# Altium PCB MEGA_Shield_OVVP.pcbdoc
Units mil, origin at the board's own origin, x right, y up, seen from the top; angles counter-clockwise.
Board outline 3935.43 x 2978.74 mil, 2 copper layers (Top Layer, Bottom Layer); 127 components, 86 nets, 395 pads, 316 vias.
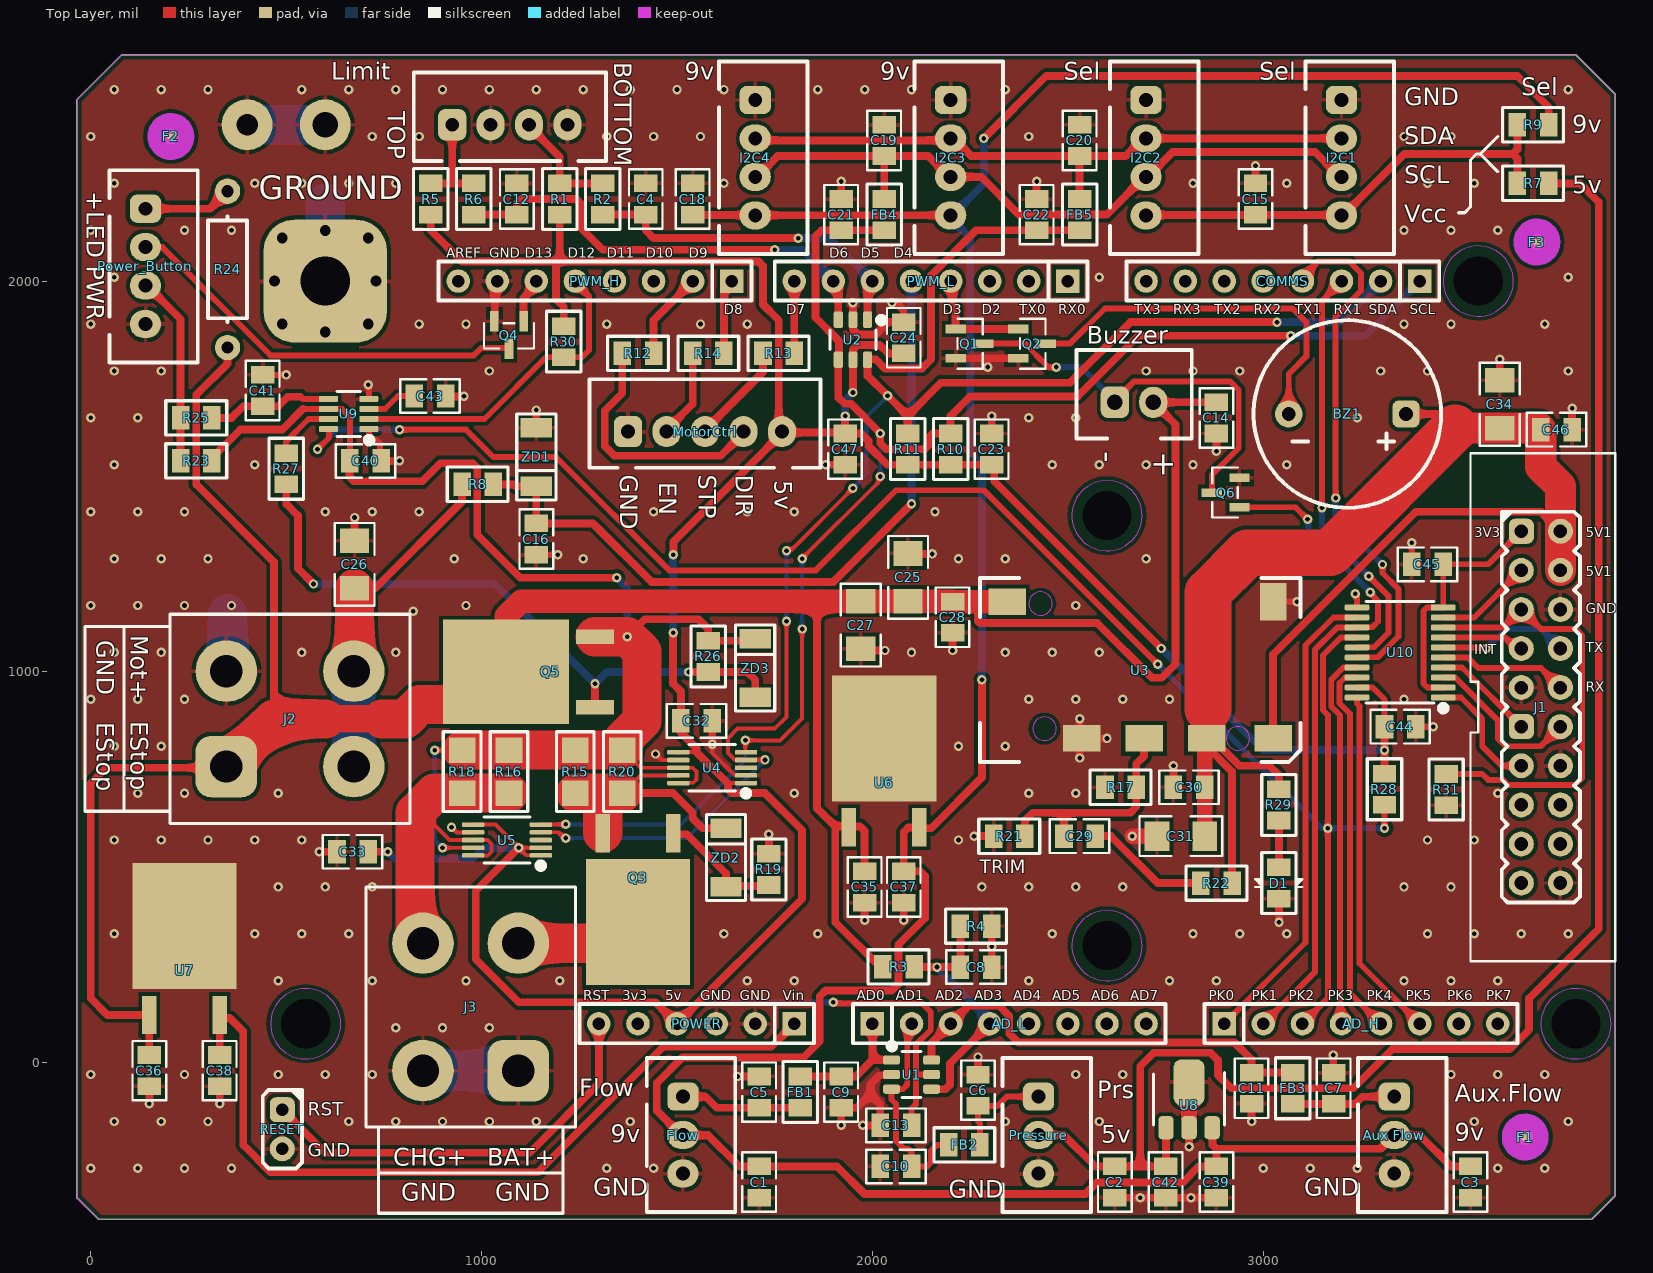
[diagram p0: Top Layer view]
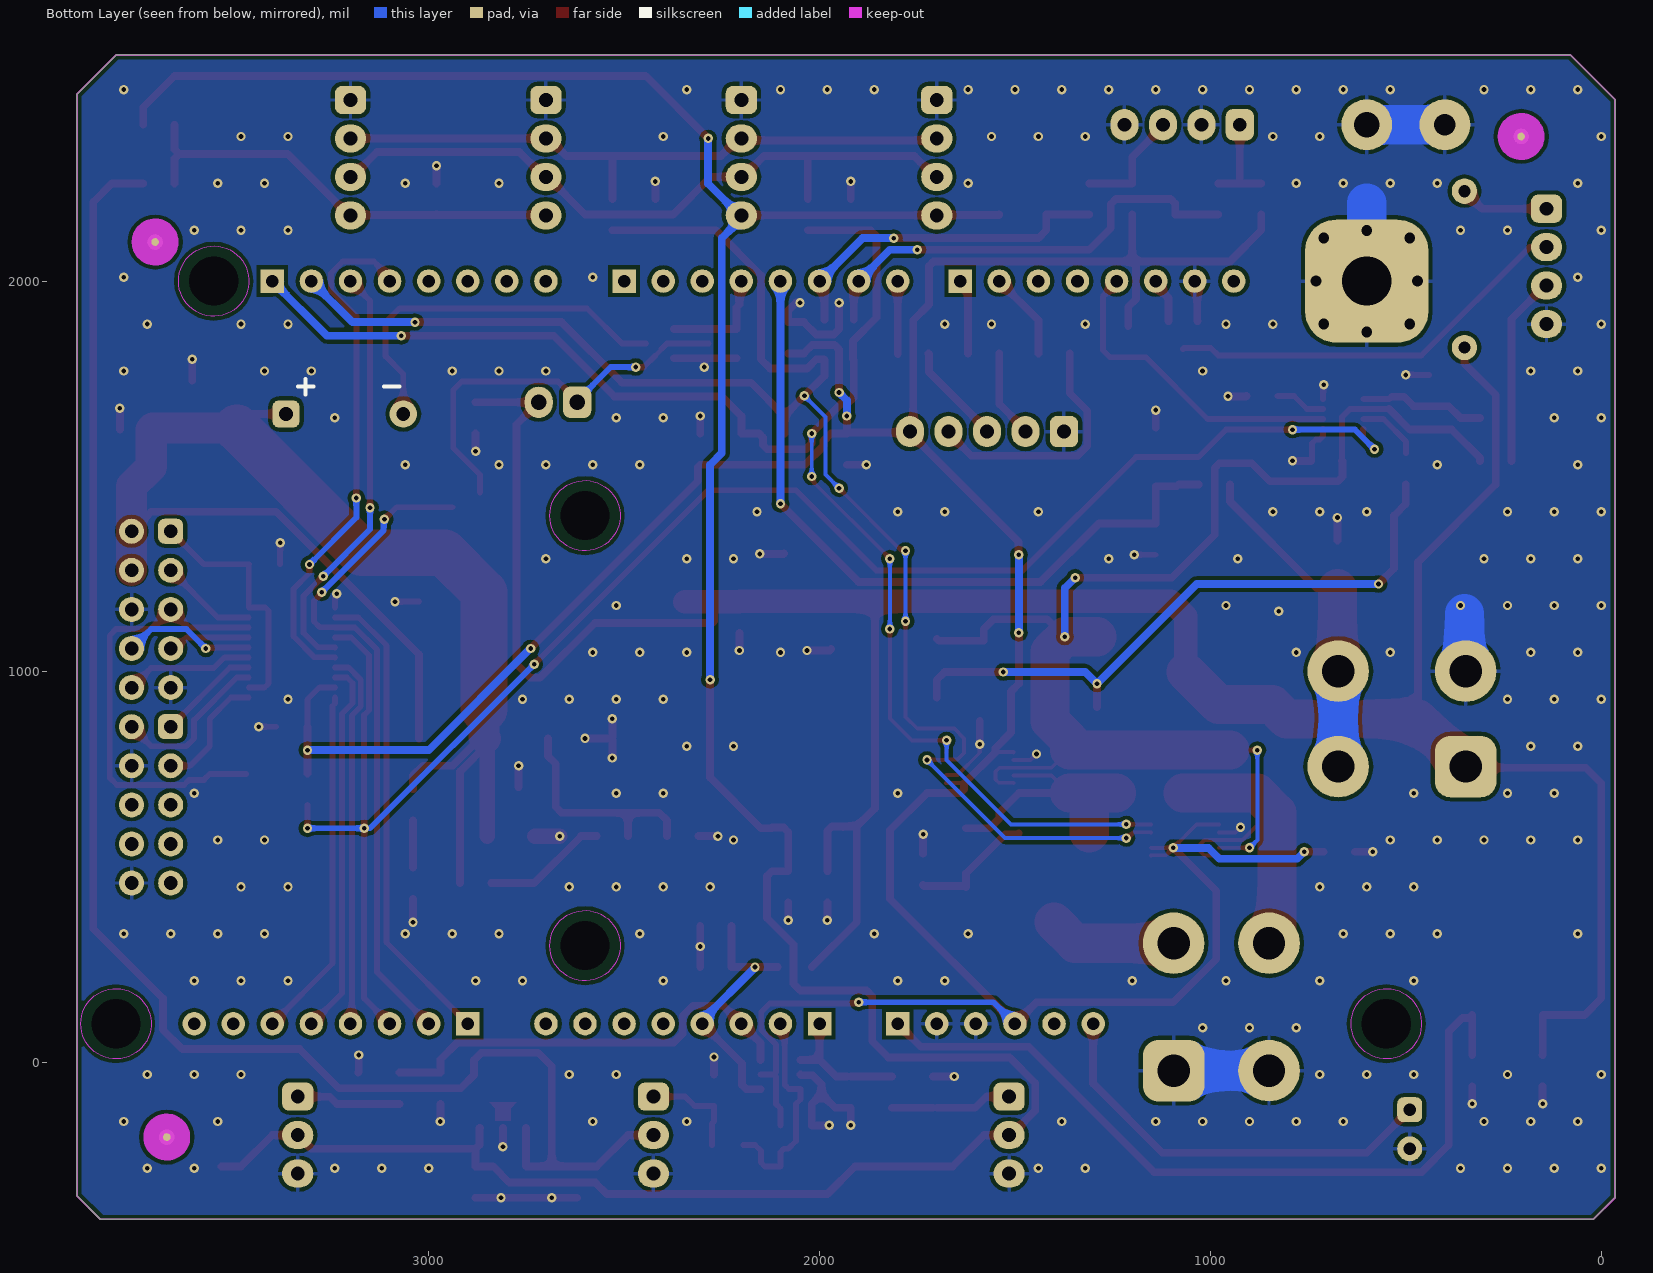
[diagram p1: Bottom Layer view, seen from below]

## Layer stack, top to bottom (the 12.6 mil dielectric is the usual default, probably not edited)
Top Solder: solder mask 0.4, Solder Resist, Dk 3.5
Top Layer: signal copper 1.4
Dielectric1: dielectric 12.6, FR-4, Dk 4.8
Bottom Layer: signal copper 1.4
Bottom Solder: solder mask 0.4, Solder Resist, Dk 3.5

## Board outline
-35.43,-344.57 20,-400 3840,-400 3900,-340 3900,50 3900,1600 3900,2477.95 3799.21,2578.74 78.74,2578.74 -35.43,2464.57

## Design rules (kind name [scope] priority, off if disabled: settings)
Clearance Bot-Poly-Clearance [InNamedPolygon('Bot-GND')] p1: gap=10 ignorepadtopadclearanceinfootprint=FALSE
Clearance Top-Poly-Clearance [InNamedPolygon('Top-GND')] p2: gap=10 ignorepadtopadclearanceinfootprint=FALSE except(0: Arc-Hole Track-Hole SMDPad-Hole THPad-Hole Via-Hole Fill-Hole Poly-Hole Region-Hole Text-Hole)
Clearance [All] p3: gap=6 ignorepadtopadclearanceinfootprint=FALSE
PolygonConnect PolygonConnect_DPAK [All vs HasFootprint('TO-252-3') OR HasFootprint('DC-DC ProLynx')] p1: connectstyle=Direct reliefconductorwidth=10 reliefentries=4 polygonreliefangle="90 Angle" airgapwidth=10
PolygonConnect PolygonConnect_Via [All vs isVia] p2: connectstyle=Direct reliefconductorwidth=10 reliefentries=4 polygonreliefangle="90 Angle" airgapwidth=10
PolygonConnect PolygonConnect_1 [All] p3: connectstyle=Relief reliefconductorwidth=10 reliefentries=4 polygonreliefangle="90 Angle" airgapwidth=10
RoutingVias [All] p1: holewidth=12 width=24 viastyle="Through Hole" minholewidth=12 minwidth=24 maxholewidth=31 maxwidth=50
SilkToSolderMaskClearance SilkscreenOverComponentPads [IsPad] p1: minsilkscreentomaskgap=10 clearancetoexposedcopper=TRUE
SolderMaskExpansion SolderMaskExpansion_Via [IsVia] p1: expansion=-39.37 soldermaskfromhole=TRUE
SolderMaskExpansion [All] p2: expansion=4
Width [All] p1: maxlimit=200 minlimit=10 preferedwidth=20
29 further rules are at their usual default settings.

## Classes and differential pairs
component class 03_RPi: C44 C45 C46 J1 R31 U10
component class 02_Power: C25 C26 C27 C28 C29 C30 C31 C32 C33 C34 C35 C36 C37 C38 C39 C40 C41 C42 C43 D1 J2 J3 Power_Button Q3 Q4 Q5 R15 R16 R17 R18 R19 R20 R21 R22 R23 R24 R25 R26 R27 R28 R29 R30 U3 U4 U5 U6 U7 U8 U9 ZD2 ZD3
component class 01_Shield: AD_H AD_L Analog "Aux Flow" Buzzer BZ1 C1 C2 C3 C4 C5 C6 C7 C8 C9 C10 C11 C12 C13 C14 C15 C16 C18 C19 C20 C21 C22 C23 C24 C47 COMMS F1 F2 F3 FB1 FB2 FB3 FB4 FB5 Flow I2C1 I2C2 I2C3 I2C4 Limit MotorCtrl POWER Pressure PWM_H PWM_L Q1 Q2 Q6 R1 R2 R3 R4 R5 R6 R7 R8 R9 R10 R11 R12 R13 R14 RESET U1 U2 ZD1

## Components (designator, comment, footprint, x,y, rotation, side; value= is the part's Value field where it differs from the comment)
AD_H "AD_H" "Header 8x1 8.5mm" 2900,100 r0 top locked
AD_L "AD_L" "Header 8x1 8.5mm" 2000,100 r0 top locked
"Aux Flow" "3pin JST" "3pin JST XH 2.5mm" 3335,-86.57 r180 top
Buzzer "2pin JST" "2pin JST XH 2.5mm" 2620,1690 r270 top
BZ1 "BUZZER, 12mm X 9.5mm" Buzzer 3365,1660 r90 top
C1 "0.1uF 50V" "C np SMD 0805" 1710,-305 r90 top
C2 "0.1uF 50V" "C np SMD 0805" 2620,-305 r90 top
C3 "0.1uF 50V" "C np SMD 0805" 3530,-305 r90 top
C4 "0.1uF 50V" "C np SMD 0805" 1420,2210 r270 top
C5 "33pF 50V" "C np SMD 0805" 1710,-75 r270 top
C6 "33pF 50V" "C np SMD 0805" 2270,-70 r270 top
C7 "33pF 50V" "C np SMD 0805" 3180,-65 r270 top
C8 "0.1uF 50V" "C np SMD 0805" 2265,245 r180 top
C9 "100pF 50V" "C np SMD 0805" 1920,-75 r90 top
C10 "100pF 50V" "C np SMD 0805" 2060,-265 r0 top
C11 "100pF 50V" "C np SMD 0805" 2970,-65 r90 top
C12 "0.1uF 50V" "C np SMD 0805" 1090,2210 r270 top
C13 "0.1uF 50V" "C np SMD 0805" 2060,-160 r0 top
C14 "0.1uF 50V" "C np SMD 0805" 2880,1650 r90 top
C15 "0.1uF 50V" "C np SMD 0805" 2980,2210 r270 top
C16 "0.1uF 50V" "C np SMD 0805" 1140,1340 r90 top
C18 "0.1uF 50V" "C np SMD 0805" 1540,2210 r270 top
C19 "33pF 50V" "C np SMD 0805" 2030,2360 r90 top
C20 "33pF 50V" "C np SMD 0805" 2530,2360 r270 top
C21 "33pF 50V" "C np SMD 0805" 1920,2170 r90 top
C22 "33pF 50V" "C np SMD 0805" 2420,2170 r270 top
C23 "0.1uF 50V" "C np SMD 0805" 2305,1570 r90 top
C24 "0.1uF 50V" "C np SMD 0805" 2080,1855 r270 top
C25 "10uF 50V" "C np SMD 1206" 2091,1242 r270 top
C26 "10uF 50V" "C np SMD 1206" 675,1275 r90 top
C27 "10uF 50V" "C np SMD 1206" 1970,1120 r90 top
C28 "0.1uF 50V" "C np SMD 0805" 2205,1140 r90 top
C29 "1nF 100V" "C np SMD 0805" 2530,580 r0 top
C30 "0.1uF 50V" "C np SMD 0805" 2810,705 r0 top
C31 "10uF 50V" "C np SMD 1206" 2789,580 r0 top
C32 "0.1uF 50V" "C np SMD 0805" 1550,875 r0 top
C33 "0.1uF 50V" "C np SMD 0805" 670,540 r180 top
C34 "10uF 50V" "C np SMD 1206" 3605,1685 r270 top
C35 "0.1uF 50V" "C np SMD 0805" 1980,450 r90 top
C36 "0.1uF 50V" "C np SMD 0805" 150,-20 r90 top
C37 "2.2uF 50V" "C np SMD 0805" 2080,450 r90 top
C38 "2.2uF 50V" "C np SMD 0805" 330,-20 r90 top
C39 "0.1uF 50V" "C np SMD 0805" 2880,-305 r90 top
C40 "0.1uF 50V" "C np SMD 0805" 703,1540 r180 top
C41 "0.1uF 50V" "C np SMD 0805" 440,1720 r270 top
C42 "2.2uF 50V" "C np SMD 0805" 2750,-305 r90 top
C43 "2.2uF 50V" "C np SMD 0805" 868,1706 r180 top
C44 "0.1uF 50V" "C np SMD 0805" 3350,860 r180 top
C45 "0.1uF 50V" "C np SMD 0805" 3420,1275.43 r0 top
C46 "0.1uF 50V" "C np SMD 0805" 3750,1620 r180 top
C47 "0.1uF 50V" "C np SMD 0805" 1930,1570 r270 top
COMMS "Communication" "Header 8x1 8.5mm" 3400,2000 r180 top
D1 "LED SMD 0805" "LED SMD 0805" 3040,460 r270 top
F1 "FIDUCIAL" FIDUCIAL 3670,-190 r0 top
F2 "FIDUCIAL" FIDUCIAL 205,2370 r270 top
F3 "FIDUCIAL" FIDUCIAL 3700,2100 r0 top
FB1 "400mA" "R SMD 0805" 1815,-75 r270 top
FB2 "400mA" "R SMD 0805" 2235,-210 r0 top
FB3 "400mA" "R SMD 0805" 3075,-65 r270 top
FB4 "400mA" "R SMD 0805" 2030,2170 r270 top
FB5 "400mA" "R SMD 0805" 2530,2170 r270 top
Flow "3pin JST" "3pin JST XH 2.5mm" 1515,-86.57 r180 top
I2C1 "4pin JST" "4pin JST XH 2.5mm" 3200,2463.43 r180 top
I2C2 "4pin JST" "4pin JST XH 2.5mm" 2700,2463.43 r180 top
I2C3 "4pin JST" "4pin JST XH 2.5mm" 2200,2463.43 r180 top
I2C4 "4pin JST" "4pin JST XH 2.5mm" 1700,2463.43 r180 top
J1 "2ROW HEADER 20PIN" "2ROW HEADER 20PIN" 3660,1360 r270 top
J2 "4pin JST VL" "4pin JST VL" 510,880 r270 top
J3 "4pin JST VL" "4pin JST VL" 972.05,142.99 r0 top
Limit "4pin JST" "4pin JST XH 2.5mm" 924.72,2400 r270 top
MotorCtrl "5pin JST" "5pin JST XH 2.5mm" 1374.72,1615 r270 top
POWER "POWER" "Header 6x1 8.5mm" 1800,100 r180 top locked
Power_Button "4pin JST" "4pin JST XH 2.5mm" 140,2185.28 r180 top
Pressure "3pin JST" "3pin JST XH 2.5mm" 2425,-86.57 r180 top
PWM_H "PWM_H" "Header 8x1 8.5mm" 1640,2000 r180 top locked
PWM_L "PWM_L" "Header 8x1 8.5mm" 2500,2000 r180 top locked
Q1 "SOT23" SOT23 2250,1840 r270 top
Q2 "SOT23" SOT23 2410,1840 r270 top
Q3 "DPAK" DPAK 1400,360 r180 top
Q4 "SOT23" SOT23 1070,1860 r180 top
Q5 "DPAK" DPAK 1062.5,1000.16 r90 top
Q6 "SOT23" SOT23 2901.78,1459.01 r90 top
R1 "4.7k" "R SMD 0805" 1200,2210 r270 top
R2 "100" "R SMD 0805" 1310,2210 r270 top
R3 "30k" "R SMD 0805" 2066.69,245.31 r0 top
R4 "10k" "R SMD 0805" 2265,350 r0 top
R5 "4.7k" "R SMD 0805" 870,2210 r270 top
R6 "100" "R SMD 0805" 980,2210 r270 top
R7 "0R" "R SMD 0805" 3690,2250 r180 top
R8 "10k" "R SMD 0805" 990,1480 r180 top
R9 "0R" "R SMD 0805" 3690,2400 r0 top
R10 "3.3k" "R SMD 0805" 2200,1570 r270 top
R11 "3.3k" "R SMD 0805" 2090,1570 r270 top
R12 "33" "R SMD 0805" 1400,1815 r0 top
R13 "33" "R SMD 0805" 1760,1815 r0 top
R14 "33" "R SMD 0805" 1580,1815 r0 top
R15 "10mOhm" "R SMD 1206" 1240,745 r90 top
R16 "10mOhm" "R SMD 1206" 1070,745 r270 top
R17 "15.8k" "R SMD 0805" 2635,705 r0 top
R18 "10mOhm" "R SMD 1206" 950,745 r270 top
R19 "1M" "R SMD 0805" 1735,495 r270 top
R20 "10mOhm" "R SMD 1206" 1360,745 r90 top
R21 "1M" "R SMD 0805" 2350,580 r0 top
R22 "270" "R SMD 0805" 2880,460 r0 top
R23 "10k" "R SMD 0805" 270,1540 r0 top
R24 "1k2" "R L10 D2.5 W6.3" 350,2030 r270 top
R25 "4.7k" "R SMD 0805" 270,1650 r0 top
R26 "200k" "R SMD 0805" 1580,1040 r90 top
R27 "100k" "R SMD 0805" 500,1520 r270 top
R28 "2k" "R SMD 0805" 3310,700 r90 top
R29 "510" "R SMD 0805" 3040,660 r270 top
R30 "10k" "R SMD 0805" 1210,1845 r90 top
R31 "2k" "R SMD 0805" 3467.54,699.03 r90 top
RESET "1ROW HEADER 2PIN" "1ROW HEADER 2PIN" 490,-120 r180 top
U1 "TPD4E001Q" SOT-23-6 2100,-30 r0 top
U2 "TPD4E001Q" SOT-23-6 1950,1850 r270 top
U3 "APXW003A0X3-SRZ" "DC-DC ProLynx" 3085,1230 r180 top
U4 "INA226" VSSOP10-TI 1590,755 r180 top
U5 "INA226" VSSOP10-TI 1065,570 r180 top
U6 "MC78M09" TO-252-3 2030,830 r0 top
U7 "MC78M09" TO-252-3 240,350 r0 top
U8 "AP7370-50Y-13" SOT-89 2810,-108.03 r90 top
U9 "LTC2955TS8-2" TSOT-23-8-LTC 660,1660 r180 top
U10 "TXs/b0108" TSSOP20-TI 3350,1050 r180 top
ZD1 "4.7V" LL34 1140,1550 r270 top
ZD2 "10V" LL34 1625,525 r90 top
ZD3 "10V" LL34 1700,1010 r90 top

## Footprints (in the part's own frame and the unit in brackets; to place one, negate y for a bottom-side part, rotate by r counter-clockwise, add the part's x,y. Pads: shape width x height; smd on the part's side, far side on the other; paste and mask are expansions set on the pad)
"1ROW HEADER 2PIN" [mil] "PEC02SAAN"
  rrect50% 64x64 hole 32: 1(0,0)
  round 64 hole 32: 2(0,100)
  silkscreen extent -50,-50 50,150
"2pin JST XH 2.5mm" [mil] "B2B-XH"
  rrect50% 80x72 hole 39.37: 1(0,0)
  oval 80x72 hole 39.37: 2(0,98.43)
  silkscreen extent -134,-98 93,197
"2ROW HEADER 20PIN" [mil]
  rrect50% 64x64 hole 35: 1(0,0) 11(500,0)
  round 64 hole 35: 2(0,100) 3(100,0) 4(100,100) 5(200,0) 6(200,100) 7(300,0) 8(300,100) 9(400,0) 10(400,100) 12(500,100) 13(600,0) 14(600,100) 15(700,0) 16(700,100) 17(800,0) 18(800,100) 19(900,0) 20(900,100)
  silkscreen extent -200,-130 1100,240
"3pin JST XH 2.5mm" [mil] "B3B-XH"
  rrect50% 80x72 hole 35.43: 1(0,0)
  oval 80x72 hole 35.43: 2(0,98.43) 3(0,196.85)
  silkscreen extent -134,-98 93,295
"4pin JST VL" [mm] "B04P-VL"
  rrect50% 4x4 hole 2.1: 1(3.1,-4.14)
  round 4 hole 2.1: 2(-3.1,-4.14) 3(3.1,4.14) 4(-3.1,4.14)
  silkscreen extent -6.8,-10.8 6.8,7.8
"4pin JST XH 2.5mm" [mil] "B4B-XH"
  rrect50% 80x72 hole 35.43: 1(0,0)
  oval 80x72 hole 35.43: 2(0,98.43) 3(0,196.85) 4(0,295.28)
  silkscreen extent -134,-98 93,394
"5pin JST XH 2.5mm" [mil] "B4B-XH"
  rrect50% 80x72 hole 35.43: 1(0,0)
  oval 80x72 hole 35.43: 2(0,98.43) 3(0,196.85) 4(0,295.28) 5(0,393.7)
  silkscreen extent -134,-98 93,492
Buzzer [mil] "PEC02SAAN"
  rrect50% 70x70 hole 35: +(0,0)
  round 70 hole 35: -(0,300)
  silkscreen extent -240,-90 240,390
"C np SMD 0805" [mil]
  rect 45x60 smd: 1(-40,0) 2(40,0)
  silkscreen extent -76,-43 76,43
"C np SMD 1206" [mil]
  rect 63x75 smd: 1(-61,0) 2(61,0)
  silkscreen extent -106,-51 106,51
"DC-DC ProLynx" [mil]
  rect 68x96 smd: ENn(60,50)
  rect 96x68 smd: GND(550,400) Trim(390,400) Vin(740,50) Vout(230,400) Vsens(60,400)
  Top Layer keep-out circle w1: c645,375 r30
  Top Layer keep-out circle w1: c655,55 r30
  Top Layer keep-out circle w1: c150,400 r30
  silkscreen extent -10,-10 810,460
DPAK [mil]
  rect 37x98 smd paste+0 mask+0: 1(-90.16,-227.5) 3(90.16,-227.5)
  rect 267x323 smd paste+0 mask+0: 2(0,0)
FIDUCIAL [mil]
  round 40 all layers, no hole paste-40 mask+40: 0(0,0)
  Top Layer keep-out circle w50: c0,0 r35
  Bottom Layer keep-out circle w50: c0,0 r35
"Header 6x1 8.5mm" [mil] "Stackable 6 pin header"
  rect 60x60 hole 32: 1(0,0)
  round 60 hole 32: 2(100,0) 3(200,0) 4(300,0) 5(400,0) 6(500,0)
  silkscreen extent -50,-50 550,50, body extent -50,-50 550,50, height 335
"Header 8x1 8.5mm" [mil] "Stackable 8 pin header"
  rect 60x60 hole 32: 1(0,0)
  round 60 hole 32: 2(100,0) 3(200,0) 4(300,0) 5(400,0) 6(500,0) 7(600,0) 8(700,0)
  silkscreen extent -50,-50 750,50, body extent -50,-50 750,50, height 335
"LED SMD 0805" [mil]
  rect 45x60 smd: A(-40,0) C(40,0)
  silkscreen extent -78,-60 78,60
LL34 [mil]
  rect 50x80 smd: A(-75,0) K(75,0)
  silkscreen extent -110,-50 110,50
"R L10 D2.5 W6.3" [mil]
  round 65 hole 31: 1(-200,0) 2(200,0)
  silkscreen extent -135,-50 135,50
"R SMD 0805" [mil]
  rect 45x60 smd: 1(-40,0) 2(40,0)
  silkscreen extent -78,-44 78,44
"R SMD 1206" [mil]
  rect 65x68 smd: 1(-55,0) 2(55,0)
  silkscreen extent -102,-48 102,48
SOT23 [mil]
  rect 22x52 smd paste+0 mask+0: 1(-37.5,-37.21) 2(37.5,-37.21) 3(0,33.36)
  silkscreen extent -64,-33 64,33
SOT-23-6 [mm]
  rrect50% 1.1x0.6 smd: 1(-1.3,0.95) 2(-1.3,0) 3(-1.3,-0.95) 4(1.3,-0.95) 5(1.3,0) 6(1.3,0.95)
  silkscreen extent -1.48,-1.5 0.63,2.05
SOT-89 [mm]
  rrect50% 1.5x1 smd: 1(-1.474,1.5) 2(-1.474,0) 3(-1.474,-1.5)
  rrect50% 3x2 smd: 2(1.474,0)
  Top Layer region: -1.026,0.5 -0.226,0.5 0.174,0.9 0.174,-0.9 -0.226,-0.5 -0.226,-0.5 -1.026,-0.5
  silkscreen extent -1.3,-2.3 2.1,2.3
TO-252-3 [mil]
  rect 37x98 smd paste+0 mask+0: 1(-90.16,-227.5) 3(90.16,-227.5)
  rect 267x323 smd paste+0 mask+0: 2(0,0)
TSOT-23-8-LTC [mm]
  rrect30% 1.22x0.4 smd mask+0.05: 1(-1.31,0.975) 2(-1.31,0.325) 3(-1.31,-0.325) 4(-1.31,-0.975) 5(1.31,-0.975) 6(1.31,-0.325) 7(1.31,0.325) 8(1.31,0.975)
  silkscreen extent -1.53,-1.45 0.75,1.9
TSSOP20-TI [mm]
  rrect50% 1.6x0.4 smd mask+0.05: 1(-2.8,2.925) 2(-2.8,2.275) 3(-2.8,1.625) 4(-2.8,0.975) 5(-2.8,0.325) 6(-2.8,-0.325) 7(-2.8,-0.975) 8(-2.8,-1.625) 9(-2.8,-2.275) 10(-2.8,-2.925) 11(2.8,-2.925) 12(2.8,-2.275) 13(2.8,-1.625) 14(2.8,-0.975) 15(2.8,-0.325) 16(2.8,0.325) 17(2.8,0.975) 18(2.8,1.625) 19(2.8,2.275) 20(2.8,2.925)
  silkscreen extent -3,-3.3 2.2,3.83
VSSOP10-TI [mm]
  rrect50% 1.45x0.3 smd mask+0.051: 1(-2.2,1) 2(-2.2,0.5) 3(-2.2,0) 4(-2.2,-0.5) 5(-2.2,-1) 6(2.2,-1) 7(2.2,-0.5) 8(2.2,0) 9(2.2,0.5) 10(2.2,1)
  silkscreen extent -2.4,-1.5 1.5,1.87

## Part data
AD_H AD_L COMMS PWM_H PWM_L: Supplier Part Number 1=2698925
BZ1: library part "Buzzer 5V"
C1 C2 C3 C4 C8 C12 C13 C14 C15 C16 C18 C23 C24 C28 C30 C32 C33 C35 C36 C39 C40 C41 C44 C45 C46 C47: library part "C 0.1uF 50V SMD 0805"
C5 C6 C7 C19 C20 C21 C22: library part "C 33pF 50V SMD 0805"
C9 C10 C11: library part "C 100pF 50V SMD 0805"
C25 C26 C27 C31 C34: library part "C 10uF 50V SMD 1206"
C29: library part "C 1nF 100V SMD 0805"
C37 C38 C42 C43: library part "C 2.2uF 50V SMD 0805"
FB1 FB2 FB3 FB4 FB5: library part "Ferrite bead SMD 0805", "400mA, 0.2ohm, 220ohm @100MHz"
POWER: Supplier Part Number 1=2699075
Q1 Q2 Q4 Q6: library part "MOSFET N-ch SOT23"
Q3 Q5: library part "MOSFET P-ch DPAK"
R1 R5 R25: library part "R 4k7 1/8W SMD 0805"
R2 R6: library part "R 100 1/8W SMD 0805"
R3: library part "R 30k 1/8W SMD 0805"
R4 R8 R23 R30: library part "R 10k 1/8W SMD 0805"
R7 R9: library part "R 0R 1/8W SMD 0805"
R10 R11: library part "R 3k3 1/8W SMD 0805"
R12 R13 R14: library part "R 33 1/8W SMD 0805"
R15 R16 R18 R20: library part "R 0.01R 1W SMD1206"
R17: library part "R 15k8 1/8W SMD 0805"
R19 R21: library part "R 1M 1/8W SMD 0805"
R22: library part "R 270 1/8W SMD 0805"
R24: library part "R 1k2 1/4W"
R26: library part "R 200k 1/8W SMD 0805"
R27: library part "R 100k 1/8W SMD 0805"
R28 R31: library part "R 2k 1/8W SMD 0805"
R29: library part "R 510 1/8W SMD 0805"
U6 U7: library part "LDO 9V TO-252"
U8: library part "LDO 5V SOT-89"
U9: library part LTC2955-2
U10: library part TX_0108
ZD1: library part "Zener 4.7V"
ZD2 ZD3: library part "Zener 10V"

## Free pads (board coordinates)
  round 62.99 hole 125.98: 0(550,100) 0(2600,300) 0(2600,1400) 0(3550,2000) 0(3800,100)
  rrect50% 314.96x314.96 hole 125.98: 0(600,2000)
  round 130 hole 55: 1(400,2400)
  round 130 hole 65: 1(600,2400)

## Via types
v1: diameter 24, hole 12, Top Layer to Bottom Layer, 305 vias
v2: diameter 50, hole 28, Top Layer to Bottom Layer, 8 vias
v3: diameter 24, hole 12, Top Layer to Bottom Layer, tented both sides, 3 vias

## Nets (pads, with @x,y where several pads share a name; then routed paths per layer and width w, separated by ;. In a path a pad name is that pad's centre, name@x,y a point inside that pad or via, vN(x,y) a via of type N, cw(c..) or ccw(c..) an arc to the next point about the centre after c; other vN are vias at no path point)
3V3A: POWER.5
5V1: BZ1.+ C30.2 C31.2 C34.2 C46.2 J1.2 J1.4 R22.2 R29.1 U3.Vout U3.Vsens | length 3935.4
  Top Layer w20: C30.2 C30.2@2855,700 ; R22.2 2920,745 2850,815 2850,825 2874,825 2939,760 3015,760 3040,735 R29.1 ; U3.Vsens 3025,1045 3390,1410 3710,1410 J1.2 ; BZ1.+ 3454,1660 3490,1624
  Top Layer w40: C31.2 C30.2 U3.Vout@2850,815 ; U3.Vout@2850,825 U3.Vout
  Top Layer w80: U3.Vout 2858.5,833.5 2858.5,890 ; 3490,1624 C34.2 3706,1624 C46.2 3710,1525 3760,1475 J1.2 J1.4
  Top Layer w120: 2858.5,904.8 2858.5,1203.5 2960,1305 3171,1305 3490,1624
5VA: C13.2 C23.1 C24.2 C32.1 C33.1 C44.2 C47.1 MotorCtrl.5 POWER.4 R1.2 R5.2 R10.2 R11.2 R28.2 R30.2 U1.5 U2.5 U4.1 U4.6 U5.1 U5.2 U5.6 U10.19 | length 8871.3
  Top Layer w10: U5.6 1035.63,609.37 v1(1095,550) ; U5.1 1151.24,531 1114,531 v1(1095,550) ; U5.2 1151.3,550 v1(1095,550) ; U4.6 1504.02,795 1550,795 ; 1630,715 1630.63,715.63 U4.1
  Top Layer w15: v1(1900,155) 1903,152 2127,152 2149,130 2149,84 2111,46 2111,-23 2118,-30 ; C13.2 2100,-117 2111,-106 2111,-37 2118,-30 ; U1.5 2118,-30 ; U10.19 3279.57,960.43 3310,930 C44.2
  Top Layer w20: C33.1 v1(760,540) ; R5.2 870,2130 950,2050 1200,2050 ; v1(1095,550) 985,440 985,265 1095,155 1445,155 POWER.4 1820,420 1820,595 1725,690 1640,690 1630,700 1630,715 1550,795 1550,805 1510,845 C32.1 1510,950 1490,970 v1(1490,1100) ; R1.2 1200,2050 ; R30.2 1210,1934 1190,1954 1190,2040 1200,2050 ; v1(1490,1300) 1490.77,1300.77 1490.77,1333.34 1768.43,1611 MotorCtrl.5 ; v1(1930,1655) C47.1 ; v1(1950,1715) U2.5 1950,1825 1961.47,1836.47 2018.53,1836.47 2040,1815 C24.2 ; v1(2739.06,1060) 2739.06,1060.94 2311.72,1488.28 2311.72,1523.28 C23.1 R10.2 R11.2 2038.23,1530 1990,1578.23 1990,1591 1971,1610 C47.1 ; R28.2 v1(3310,800) C44.2 ; 1200,2050 1708.28,2050 1720,2038.28 1720,1940 1760,1900 1760,1623.43 MotorCtrl.5 ; MotorCtrl.5 1770.93,1612.5 1927.5,1612.5 C47.1
  Bottom Layer w15: POWER.4 1555,155 v1(1900,155)
  Bottom Layer w20: v1(760,540) 778,522 977.16,522 1005.16,550 v1(1095,550) ; v1(1490,1100) v1(1490,1300) ; v1(1930,1655) 1930,1695 v1(1950,1715) ; v1(2739.06,1060) 2740,1060 3000,800 v1(3310,800)
5VS: C2.2 C42.2 Pressure.2 R7.1 U8.1 | length 4183.7
  Top Layer w20: Pressure.2 2490,-185 2570,-265 C2.2 2685,-265 ; U8.1 2750.94,-264.06 C42.2 2685,-265 ; R7.1 3810,2250 3858,2202 3858,343 3680,165 3680,85 3630,35 3330,35 3230,-65 2918,-65 2884,-31 2884,7 2865,26 2720,26 2685,-9 2685,-265
9VS: "Aux Flow.2" C1.2 C3.2 C18.2 C37.2 C39.2 Flow.2 I2C3.4 I2C4.4 R9.2 U6.3 U8.3 | length 7890.8
  Top Layer w20: C18.2 1540.93,2169.07 1699.07,2169.07 I2C4.4 1700.35,2168.5 2199.65,2168.5 I2C3.4 ; v1(2280,980) 2280,730 2150,600 2122.66,600 U6.3 2119.66,602 2091.72,602 2080,590.28 C37.2 2122,490 2134,478 2134,370 2067,303 2067,203 2049,185 1880,185 1865,170 1865,55 1824,14 1514,14 1448,-52 1448,-122 1511,-185 Flow.2 1579,-185 1659,-265 C1.2 1909,-265 1979.43,-335.43 2544.57,-335.43 2573.5,-306.5 2793.5,-306.5 2835,-265 C39.2 2880,-220 ; v1(2285,2365) 2445,2525 3650,2525 3730,2445 R9.2 ; U8.3 2870,-167.01 2870,-210 2880,-220 ; C3.2 3480,-265 3400,-185 3335,-185 3300,-220 2880,-220
  Bottom Layer w20: v1(2280,980) 2280,1530 2250,1560 2250,2110 2200,2160 I2C3.4 2204,2168.15 2285,2249.15 v1(2285,2365)
AD0: AD_L.1 C9.2 FB1.1 U1.1 | length 334
  Top Layer w20: FB1.1 C9.2 ; C9.2@1930,-35 1957,-35 1999.4,7.4 2000,7.4 ; AD_L.1 2000,7.4 ; U1.1 2000,7.4
AD1: AD_L.2 C10.2 FB2.1 U1.3 | length 566.2
  Top Layer w15: AD_L.2 2089,89 2089,-56 2078,-67 2049.22,-67 U1.3 2048.82,-93.82 2060,-105 2060,-200 2080,-220 2091.21,-220 2100,-228.79 C10.2 2140,-265 2150,-255 2150,-225 2165,-210 FB2.1
AD2: AD_L.3 C11.2 FB3.1 U1.6 | length 1123.6
  Top Layer w20: U1.6 2151.18,51.18 AD_L.3 2246,146 2324,146 2350,120 2350,75 2373,52 2926.28,52 2970,8.28 C11.2 FB3.1
AD3: AD_L.4 C8.2 R3.2 R4.1 U1.4 | length 674.4
  Top Layer w20: R3.2 2107.01,245 v1(2165,245) C8.2 R4.1 ; U1.4 2187,-67.4 2198,-56.4 2198,-2 AD_L.4
  Bottom Layer w20: v1(2165,245) 2165,243.92 2300,108.92 AD_L.4
AD4: AD_L.5
AD5: AD_L.6
AD6: AD_L.7
AD7: AD_L.8
AREF: PWM_H.8
BAT+: C40.2 Q5.3 R15.2 R16.1 R18.1 R20.2 R23.2 R26.2 U4.8 U4.10 U5.9 U9.6 ZD3.K | length 3563.1
  Top Layer w10: v1(880,800) R18.1 ; v1(900,550) 900.32,550.32 U5.9 ; R20.2 1361.5,800 1406.5,755 U4.8 1540,755 1550,745 1550,725 1541.54,716.54 1504.29,716.54 U4.10
  Top Layer w15: 542.8,1672.8 U9.6 608.8,1672.42 643.58,1672.42 663,1653 C40.2
  Top Layer w20: R23.2 310,1547.5 382.5,1620 490,1620 542.8,1672.8 ; C40.2 662,1539 662,1499.72 673.72,1488 848,1488 894,1534 977,1534 989,1522 989,1351 1099,1241 v1(1346,1241) ; v1(1372.5,1090.16) 1417.34,1135 1555,1135 1580,1110 R26.2 1695,1080 ZD3.K
  Top Layer w100: R18.1 R16.1 R15.2 R20.2 1360,825 1410,875 1410,1052.66 v1(1372.5,1090.16) 1290.16,1090.16 Q5.3
  Bottom Layer w10: v1(880,800) 880,570 v1(900,550)
  Bottom Layer w20: v1(1346,1241) 1372.5,1214.5 v1(1372.5,1090.16)
BCM2: J1.3 U10.9 | length 249.6
  Top Layer w15: U10.9 3539.57,1139.57 J1.3
BCM3: J1.5 R31.2 U10.8 | length 1134.4
  Top Layer w15: U10.8 3613.98,1113.98 J1.5 3709.76,1110.24 3799.21,1110.24 3815.94,1093.5 3815.94,729.33 3797.24,710.63 3625.98,710.63 3612.58,724.03 3575.18,724.03 3560.18,739.03 R31.2
BCM4: J1.7 U10.7 | length 211.5
  Top Layer w15: U10.7 3618.35,1088.39 3646.74,1060 J1.7
BCM17: J1.11 U10.4 | length 262.6
  Top Layer w15: U10.4 3508.39,1011.61 J1.11
BCM18: J1.12 U10.3 | length 420.8
  Top Layer w15: U10.3 3460.61,985.65 3491.18,985.65 3600,876.82 3600,830 3620,810 3710,810 J1.12
BCM27: J1.13 U10.1 | length 313.2
  Top Layer w15: U10.1 3460.61,934.47 3505.53,934.47 3560,880 3560,810 3610,760 J1.13
BIN+: J3.3 Q3.2 | length 328.3
  Top Layer w100: J3.3 1345.98,305.98 Q3.2
CHRG+: J3.4 R16.2 R18.2 U5.8 U5.10 | length 920.4
  Top Layer w10: 880,690 880,608 918,570 U5.8 1015,570 1025,560 1025,540 1015.63,530.63 U5.10
  Top Layer w100: J3.4 850,321.54 830,341.54 830,640 880,690 R18.2 R16.2
D2: PWM_L.3
D3: PWM_L.4 Q1.1 Q2.1 | length 287.8
  Top Layer w20: PWM_L.4 2205,1995 2205,1940 2212.79,1932.21 Q1.1 Q2.1
D4: C16.2 PWM_L.5 R8.1 ZD1.K | length 1882
  Top Layer w20: R8.1 1081,1480 1086,1475 ZD1.K C16.2 1285,1380 1435,1230 1900,1230 v1(2100,1430)
  Bottom Layer w20: v1(2100,1430) PWM_L.5
D5: C4.2 PWM_L.6 R2.2 U2.1 | length 887.9
  Top Layer w20: R2.2 C4.2 1420,2130 1440,2110 v1(1810,2110) ; U2.1 1987.4,1976.58 2000,1989.18 PWM_L.6
  Bottom Layer w20: v1(1810,2110) 1890,2110 PWM_L.6
D6: C12.2 PWM_L.7 R6.2 U2.3 | length 1180.5
  Top Layer w20: R6.2 C12.2 1090,2198.28 1101.72,2210 1242,2210 1255,2197 1255,2135 1310,2080 v1(1750,2080) ; PWM_L.7 1900,1989.18 1912.6,1976.58 U2.3
  Bottom Layer w20: v1(1750,2080) 1820,2080 PWM_L.7
D7: PWM_L.8 R13.2 | length 187
  Top Layer w20: R13.2@1800,1813 PWM_L.8
D8: PWM_H.1 R14.2 | length 193.3
  Top Layer w20: R14.2 1620,1980 PWM_H.1
D9: PWM_H.2 R12.2 | length 226.4
  Top Layer w20: R12.2 1440,1900 PWM_H.2
D10: PWM_H.3
D11: PWM_H.4
D12: PWM_H.5 R30.1 U9.2 | length 827.7
  Top Layer w15: U9.2 1007.2,1647.2 1165,1805 R30.1 1257,1805 1275,1823 1275,1960.75 1240,1995.75 PWM_H.5
D13: PWM_H.6 Q4.1 | length 116.2
  Top Layer w20: Q4.1 1107.5,1956.68 1140,1989.18 PWM_H.6
GND: "Aux Flow.3" C1.1 C2.1 C3.1 C4.1 C5.1 C6.1 C7.1 C8.1 C9.1 C10.1 C11.1 C12.1 C13.1 C14.1 C15.1 C16.1 C18.1 C19.2 C20.1 C21.2 C22.1 C23.2 C24.1 C25.1 C26.2 C27.1 C28.1 C30.1 C31.1 C32.2 C33.2 C34.1 C35.1 C36.1 C37.1 C38.1 C39.1 C40.1 C41.1 C42.1 C43.1 C44.1 C45.1 C46.1 C47.2 D1.C Flow.3 I2C1.1 I2C2.1 I2C3.1 I2C4.1 J1.6 J1.9 J1.14 J1.20 J2.2 J3.1 J3.2 Limit.2 Limit.4 MotorCtrl.1 pad.0@600,2000 pad.1 POWER.2 POWER.3 Power_Button.4 Pressure.3 PWM_H.7 Q1.2 Q2.2 Q4.2 Q6.2 R4.2 R17.1 R19.1 R21.1 R31.1 RESET.2 U1.2 U2.2 U3.ENn U3.GND U4.2 U4.7 U5.7 U6.2 U7.2 U8.2 U9.1 U9.4 U10.11 ZD1.A | length 5017
  Top Layer w10: v1(923,603) 936.32,589.68 U5.7 ; v1(1445,790) 1460.32,774.68 U4.7 ; v1(1590,815) 1590,793.34 1647.12,736.22 1675.71,736.22 U4.2
  Top Layer w15: C41.1 v1(500,1760) ; v3(710,1735) 711.57,1733.43 U9.4 ; U9.1 711.57,1603.79 720.36,1595 730,1595 740,1585 740,1543 C40.1 ; C16.1 v1(1195,1300) ; U3.ENn v1(3086,1180) ; v1(3235,1200) 3239.76,1195.24 U10.11 ; C45.1 v1(3380,1330.43) ; C44.1 v1(3435,860)
  Top Layer w20: v1(150,-105) C36.1 ; v1(330,-105) C38.1 ; v2(490,1890) pad.0@600,2000 ; v2(490,2110) pad.0@600,2000 ; v1(585,540) C33.2 ; C26.2 v1(675,1395) ; v2(710,1890) pad.0@600,2000 ; v2(710,2110) pad.0@600,2000 ; C40.1 v1(790,1540) ; C43.1 909,1705 v1(955,1705) ; Q4.2 1033.5,1898.21 1033.5,1993.5 PWM_H.7 ; ZD1.A v1(1140,1670) ; v1(1590,815) C32.2 ; v1(1655,-35) C5.1 ; R19.1 v1(1735,585) ; v1(1880,1530) C47.2 ; v1(1920,-160) C9.1 1960,-115 1995,-80 ; C21.2 v1(1920,2255) ; v1(1950,1945) U2.2 1950,1877.05 1963.53,1863.53 2008.53,1863.53 2040,1895 C24.1 2080,1925 2060,1945 v1(2050,1945) ; C27.1 1974,1055 v1(2032,1055) ; v1(1975,-160) C13.1 2020,-105 1995,-80 ; v1(1980,365) C35.1 ; U1.2 2047.01,-31.81 2018.19,-31.81 1995,-55 1995,-80 ; v1(2080,365) C37.1 ; C25.1 2092,1302 v1(2153,1302) ; v1(2205,1055) C28.1 ; Q1.2 2292.79,1802.5 ; v1(2260,580) R21.1 ; C6.1 v1(2270,15) ; v1(2295,1780) 2294.23,1780.77 2294.23,1801.05 2292.79,1802.5 ; C8.1 v1(2305,297.5) R4.2 ; C23.2 v1(2305,1655) ; Q2.2 2292.79,1802.5 ; C22.1 v1(2420,2255) ; v1(2530,780) 2530,825 U3.GND ; v1(2530,880) 2530,835 U3.GND ; v1(2600,830) U3.GND ; C2.1 v1(2685,-345) C42.1 v1(2815,-345) C39.1 ; C30.1 v1(2770,760) ; v1(2810,-215) U8.2@2810,-166.06 ; v1(2880,1565) C14.1 ; v1(2970,-150) C11.1 ; C15.1 v1(2980,2295) ; v1(3040,360) D1.C ; v1(3179,20) 3179,-24 C7.1 ; C34.1 v1(3605,1800) ; C46.1 v1(3790,1675)
  Top Layer w40: v1(2665,580) C31.1
  Bottom Layer w100: J2.2 350,1005.04 350,1150 ; pad.1@400,2400 pad.1@600,2400 ; v2(600,2130) 600,2200 ; J3.2 J3.1
  other v1: 0,-270 120,-270 240,-270 360,-270 1320,-270 1440,-270 3000,-270 3120,-270 3240,-270 3600,-270 3720,-270 60,-150 180,-150 300,-150 660,-150 780,-150 900,-150 1020,-150 1140,-150 1380,-150 2340,-150 2580,-150 3540,-150 3780,-150 0,-30 240,-30 480,-30 600,-30 720,-30 2520,-30 2640,-30 3480,-30 3600,-30 3720,-30 780,90 900,90 1020,90 480,210 720,210 960,210 1200,210 1680,210 1800,210 2400,210 2760,210 2880,210 3360,210 3480,210 3600,210 60,330 420,330 540,330 660,330 1620,330 1860,330 2460,330 2820,330 2940,330 3060,330 3420,330 3540,330 3660,330 3780,330 480,450 600,450 720,450 2280,450 2400,450 2520,450 2640,450 3360,450 3480,450 60,570 180,570 300,570 420,570 540,570 2220,570 3420,570 3540,570 120,690 240,690 480,690 1800,690 2400,690 2520,690 3600,690 60,810 180,810 2220,810 2340,810 0,930 120,930 240,930 2400,930 2520,930 2640,930 2760,930 3360,930 60,1050 180,1050 540,1050 780,1050 2100,1050 2340,1050 2460,1050 2580,1050 825,1155 0,1170 120,1170 240,1170 360,1170 960,1170 2520,1170 60,1290 180,1290 300,1290 930,1290 1260,1290 2220,1290 2340,1290 2700,1290 0,1410 120,1410 240,1410 600,1410 720,1410 840,1410 1440,1410 1680,1410 1800,1410 2160,1410 60,1530 420,1530 2460,1530 2580,1530 2700,1530 2820,1530 3060,1530 0,1650 120,1650 2400,1650 2520,1650 3240,1650 60,1770 180,1770 1020,1770 2700,1770 2820,1770 2940,1770 3300,1770 3420,1770 3780,1770 0,1890 840,1890 960,1890 1320,1890 1560,1890 1680,1890 3360,1890 3480,1890 3720,1890 60,2010 2580,2010 3780,2010 0,2130 240,2130 360,2130 3360,2130 3480,2130 3600,2130 60,2250 420,2250 540,2250 660,2250 780,2250 1620,2250 2820,2250 3060,2250 3420,2250 3540,2250 0,2370 720,2370 840,2370 1320,2370 1440,2370 1560,2370 2400,2370 3360,2370 3480,2370 60,2490 180,2490 300,2490 540,2490 660,2490 780,2490 900,2490 1020,2490 1140,2490 1260,2490 1380,2490 1500,2490 1620,2490 1860,2490 1980,2490 2100,2490 2340,2490 3780,2490
  other v2: 600,1870 470,2000 730,2000
HV: Buzzer.2 C14.2 C25.2 C27.2 C28.2 C35.2 C36.2 J2.1 Q5.2 R3.1 R24.2 U3.Vin U6.1 U7.1 | length 7190
  Top Layer w20: C36.2 149.84,20.16 U7.1 42.5,122.5 0,165 0,715 40,755 344.06,755 J2.1 ; R24.2 350,1788.91 270,1708.91 270,1480 469.06,1280.94 469.06,880 ; 1858,1181 1858,651 1904,605 ; C35.2 1980,593.28 1968.28,605 1942.34,605 U6.1 1937.34,605 1904,605 ; R3.1@2019.69,245.31 1905,360 1905,604 1904,605 ; 2275,1180 2270,1175 2270,1130 2275,1125 2575,1125 2715,985 2740,985 2775,1020 2775,1633.43 Buzzer.2 C14.2
  Top Layer w40: U3.Vin U3.Vin@2350,1185
  Top Layer w60: Q5.2 1062.5,1142.5 1101,1181 1858,1181 C27.2 C25.2 2204,1181 C28.2 2275,1180 U3.Vin
  Top Layer w70: 600,880 745,880
  Top Layer w100: J2.1 469.06,880 600,880 ; 745,880 805,880 841.66,916.66 979,916.66 Q5.2
HV_Motor: C26.1 J2.3 J2.4 R8.2 | length 867.8
  Top Layer w20: C26.1 728,1214 950,1436 R8.2
  Top Layer w100: J2.4 675,1004.05 C26.1
  Bottom Layer w100: J2.3 J2.4
IBAT: Q3.3 R15.1 R20.1 U4.9 ZD2.K | length 698.3
  Top Layer w10: R20.1@1361.5,690 1406.82,735.32 U4.9
  Top Layer w20: R20.1 1361.5,690 1490,690 1540,640 1540,625 1565,600 ZD2.K
  Top Layer w100: R15.1 1300,690 ; Q3.3 1309.84,680.16 1300,690 ; R20.1 1300,690
"NetAux Flow_1": "Aux Flow.1" C7.2 FB3.2 | length 267.6
  Top Layer w20: FB3.2 C7.2 3235,-105 3253.43,-86.57 3335,-86.57
NetBuzzer_1: Buzzer.1 Q1.3 Q6.3 | length 1043.5
  Top Layer w12: 2403.86,1827 2405.36,1825.5 2405.36,1824.03 2419.39,1810
  Top Layer w15: Q1.3 2390.86,1840 2403.86,1827 ; 2419.39,1810 2449.39,1780 v1(2470,1780) ; Buzzer.1 2620,1694 2669.5,1743.5 2914.96,1743.5 2937.01,1721.46 2937.01,1572.83 2868.42,1504.25 Q6.3
  Bottom Layer w15: v1(2470,1780) 2534,1780 2620,1694 Buzzer.1
NetBZ1_-: BZ1.- Q2.3 | length 972.1
  Top Layer w15: Q2.3 2505,1840 2595,1930 3075,1930 3110,1895 3110,1807.44 3065,1762.44 BZ1.-
NetC5_2: C5.2 FB1.2 Flow.1 | length 301.8
  Top Layer w20: Flow.1 1573.57,-86.57 1602,-115 C5.2@1700,-115 ; C5.2 FB1.2
NetC6_2: C6.2 FB2.2 Pressure.1 | length 266.8
  Top Layer w15: FB2.2 2275,-155 2270,-150 C6.2 2320,-110 2343.43,-86.57 Pressure.1
NetC15_2: C15.2 I2C1.4 I2C2.4 R7.2 R9.1 | length 1164.5
  Top Layer w20: I2C2.4 2700.93,2169.07 2979.07,2169.07 C15.2 2980.93,2169.07 3199.07,2169.07 I2C1.4 3204,2168.15 3360.85,2325 3638.28,2325 ; R7.2 3650,2313.28 3638.28,2325 ; R9.1 3650,2336.72 3638.28,2325
NetC19_1: C19.1 FB4.1 I2C1.3 I2C2.3 I2C3.3 I2C4.3 | length 1786.8
  Top Layer w20: I2C4.3 1704,2266.57 1757.43,2320 C19.1 ; FB4.1 C19.1 ; I2C1.3 3196,2266.57 3132.57,2330 2767.43,2330 2704,2266.57 I2C2.3 2696,2266.57 2599.43,2170 2374.8,2170 2278.22,2266.57 I2C3.3 2196,2266.57 2142.57,2320 C19.1
NetC20_2: C20.2 FB5.1 I2C1.2 I2C2.2 I2C3.2 I2C4.2 | length 1651.4
  Top Layer w20: I2C4.2 1705,2360 2195,2360 I2C3.2 2207.34,2365 2252.34,2320 C20.2 ; FB5.1 C20.2 ; I2C1.2 I2C2.2 2692.66,2365 2647.66,2320 C20.2
NetC29_1: C29.1 R17.2 R21.2 U3.Trim | length 582.8
  Top Layer w20: R21.2 2390,620 2410,640 2490,640 ; C29.1 2490,640 ; U3.Trim 2695,785 2675,765 R17.2 2675,655 2660,640 2490,640
NetC29_2: C29.2 R22.1 | length 319.7
  Top Layer w20: C29.2 2610,580 2730,460 R22.1
NetC41_2: C41.2 R25.2 U9.5 | length 323.3
  Top Layer w15: 535.81,1704.19 541.61,1698.39 U9.5
  Top Layer w20: R25.2 360,1650 390,1680 C41.2 480,1680 504.19,1704.19 535.81,1704.19
NetC43_2: C43.2 U9.3 | length 130.2
  Top Layer w15: U9.3 752.8,1672.8 786,1706 C43.2
NetD1_A: D1.A R29.2 | length 120
  Top Layer w20: D1.A R29.2
NetLimit_1: Limit.1 R5.1 R6.1 | length 260.1
  Top Layer w20: R5.1 925,2250 ; Limit.1 924.72,2250.28 925,2250 ; R6.1 925,2250
NetLimit_3: Limit.3 R1.1 R2.1 | length 292.5
  Top Layer w20: Limit.3 1121.57,2396 1200,2317.57 R1.1 R2.1
NetMotorCtrl_2: MotorCtrl.2 R14.1 | length 227.7
  Top Layer w20: MotorCtrl.2 1473.15,1619 1540,1685.85 R14.1
NetMotorCtrl_3: MotorCtrl.3 R13.1 | length 261.9
  Top Layer w20: MotorCtrl.3 1571.57,1619 1720,1767.43 1720,1814 R13.1@1721,1815
NetMotorCtrl_4: MotorCtrl.4 R12.1 | length 649
  Top Layer w20: R12.1 1360,1713 1315,1668 1315,1578 1340,1553 1612,1553 1670,1611 MotorCtrl.4
NetPower_Button_1: Power_Button.1 R24.1 | length 228.5
  Top Layer w20: Power_Button.1 305.28,2185.28 R24.1
NetPower_Button_2: Power_Button.2 Q4.3 | length 1073.5
  Top Layer w15: Power_Button.2@120,2086.85 Power_Button.2 183.15,2086.85 460,1810 980,1810 999.02,1829.02 1067.62,1829.02 Q4.3
NetPower_Button_3: Power_Button.3 R23.1 R25.1 | length 503.4
  Top Layer w20: Power_Button.3@120,1988.43 124,1988.43 Power_Button.3@132,1980.43 ; Power_Button.3 144,1988.43 230,1902.43 R25.1 R23.1
NetQ3_G: Q3.1 R19.2 ZD2.A | length 324.4
  Top Layer w20: Q3.1 1492.66,585 1525,585 1625,485 ZD2.A 1627.5,452.5 1732.5,452.5 R19.2
NetQ5_G: Q5.1 R26.1 R27.2 ZD3.A | length 1645.3
  Top Layer w20: R27.2 500,1430 530,1400 530,1265 v1(570,1225) ; Q5.1 v1(1290,970) ; v1(1530,1000) R26.1 1680,1000 1700,980 ZD3.A
  Bottom Layer w20: v1(570,1225) 1035,1225 v1(1290,970) 1320,1000 v1(1530,1000)
NetR27_1: R27.1 U9.7 | length 162.1
  Top Layer w15: R27.1 500,1590 557.2,1647.2 U9.7
PK0: AD_H.1 U10.12 | length 1215.6
  Top Layer w15: AD_H.1 3108,308 3108,1068 3179.57,1139.57 U10.12
PK1: AD_H.2 Q6.1 U10.13 | length 1726.1
  Top Layer w15: Q6.1 3082.43,1421.51 v3(3113.19,1390.75) ; AD_H.2 3131.77,231.77 3131.77,1056.77 3188.98,1113.98 U10.13 3240.14,1114.35 3278.72,1114.35 3293.31,1128.94 3293.31,1181.62 3273.62,1201.3 v3(3273.62,1203.74)
  Bottom Layer w15: v3(3113.19,1390.75) 3114.91,1389.03 3114.91,1383.12 3115.16,1382.87 3115.16,1362.2 v3(3273.62,1203.74)
PK2: AD_H.3 R28.1 U9.8 U10.14 | length 4549.1
  Top Layer w15: v1(580,1570) 610,1600 610,1621.24 609.63,1621.61 U9.8 ; v1(790,1620) 960,1620 1030,1550 1190,1550 1480,1260 1855,1260 2060,1465 2285,1465 v1(2730,1020) ; AD_H.3 3165,165 v1(3165,600) 3165,890 3152.77,902.23 3152.77,1042.77 3198.39,1088.39 U10.14 ; v1(3310,600) R28.1
  Bottom Layer w15: v1(580,1570) 630,1620 v1(790,1620) ; v1(2730,1020) 3150,600 v1(3165,600) v1(3310,600)
PK3: AD_H.4 U10.17 | length 970.1
  Top Layer w15: AD_H.4 3196.5,103.5 3196.5,888.8 3173.77,911.53 3173.77,980.29 3204.72,1011.24 3239.39,1011.24 U10.17
PK4: AD_H.5 U10.18 | length 966.2
  Top Layer w15: U10.18 3239.39,985.65 3208.82,985.65 3194.77,971.59 3194.77,920.23 3222,893 3222,178 AD_H.5
PK5: AD_H.6 U10.20 | length 901.2
  Top Layer w15: U10.20 3239.76,919.24 3246,913 3246,254 AD_H.6
PK6: AD_H.7
PK7: AD_H.8
RESET: POWER.6 RESET.1 | length 1081.9
  Top Layer w20: RESET.1 600,-230 1123,-230 1300,-53 POWER.6
RP3V3: C45.2 J1.1 U10.2 U10.10 | length 640.1
  Top Layer w15: U10.2 3459.86,960.06 3420.06,960.06 3410,970.12 3410,1156.37 3418.41,1164.78 3459.86,1164.78 U10.10 3460.24,1240 3460.24,1275.2 C45.2 3575.43,1275.43 J1.1
RPRXD: J1.10 U10.5 | length 331.7
  Top Layer w15: U10.5 3522.8,1037.2 3550,1010 3710,1010 J1.10
RPTXD: J1.8 U10.6 | length 342.3
  Top Layer w15: U10.6 3545.72,1062.8 3546.79,1061.72 3568.28,1061.72 v1(3570,1060)
  Bottom Layer w15: v1(3570,1060) 3620,1110 3710,1110 J1.8
RX0: PWM_L.1
RX1: COMMS.3 U10.15 | length 1086.7
  Top Layer w15: v1(3150,1420) 3150,1950 COMMS.3 ; U10.15 3240.14,1063.17 3283.17,1063.17 3319.88,1099.88 3319.88,1195.12 v1(3270,1245)
  Bottom Layer w15: v1(3150,1420) 3150,1365 v1(3270,1245)
RX2: COMMS.5
RX3: COMMS.7
SCL: C21.1 COMMS.1 FB4.2 R10.1 U2.4 U4.5 U5.5 | length 4046.5
  Top Layer w10: U5.5 1152.24,610 v1(1215,610) ; U4.5 1675.91,794.37 1675,795.28 v1(1675,825) 1763.89,825 1820,881.11 v1(1820,1110) ; v1(1820,1290) 2020,1490 v1(2020,1500)
  Top Layer w20: FB4.2 C21.1 1870,2130 1854,2114 1854,1907.15 1914.41,1846.74 1914.41,1800.63 U2.4 1912.6,1702.4 1929,1686 1945,1686 2020,1611 v1(2020,1610) 2020,1585 2035,1570 2133.5,1570 2145,1581.5 2145,1600 2155,1610 R10.1 2200,1655 2250,1705 2525,1705 2680,1860 v1(3070,1860)
  Bottom Layer w10: v1(1215,610) 1510,610 1675,775 v1(1675,825) ; v1(1820,1110) v1(1820,1290) ; v1(2020,1500) v1(2020,1610)
  Bottom Layer w20: v1(3070,1860) 3260,1860 COMMS.1
SDA: C22.2 COMMS.2 FB5.2 R11.1 U2.6 U4.4 U5.4 | length 4319
  Top Layer w10: U5.4 1151.93,590 1196.21,590 1211.21,575 v1(1215,575) ; v1(1725,775) 1676.93,775 U4.4 1675.71,775.59 1647.12,775.59 1630,792.71 1630,830 1655,855 1750,855 1780,885 v1(1780,1130) ; v1(1780,1310) 1790,1310 v1(1950,1470)
  Top Layer w20: R11.1 2090,1655 ; FB5.2 C22.2 2264.95,2130 2150,2015.05 2150,1800 2126.5,1776.5 2031.78,1776.5 2008.28,1800 1988.58,1800 U2.6 1987.4,1757.6 v1(2038.7,1706.3) 2090,1655 ; v1(3035,1895) 2660,1895 2505,1740 2175,1740 2090,1655
  Bottom Layer w10: v1(1215,575) 1525,575 v1(1725,775) ; v1(1780,1130) v1(1780,1310) ; v1(1950,1470) 1985,1505 1985,1652.6 v1(2038.7,1706.3)
  Bottom Layer w20: v1(3035,1895) 3195,1895 COMMS.2
TX0: PWM_L.2
TX1: COMMS.4 U10.16 | length 1339.7
  Top Layer w15: COMMS.4 3100,2010 3140,2050 3220,2050 3250,2020 3250,1975 3185,1910 v1(3185,1445) ; U10.16 3240.14,1037.58 3292.58,1037.58 3345.47,1090.47 3345.47,1212.6 3305,1253.07 v1(3305,1275)
  Bottom Layer w15: v1(3185,1445) 3185,1395 v1(3305,1275)
TX2: COMMS.6
TX3: COMMS.8
VIN: C38.2 POWER.1 U7.3 | length 2066.4
  Top Layer w20: C38.2 330.16,20.16 U7.3 337.66,115 355,115 390,80 390,-210 460,-280 1144,-280 1465,41 1741,41 POWER.1
pads on no net: F1.0 F2.0 F3.0 J1.15 J1.16 J1.17 J1.18 J1.19 U4.3 U5.3

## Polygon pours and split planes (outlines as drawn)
GND on Bottom Layer "Bot-GND" (solid, remove dead copper, pour order 0): -35.43,-400 -35.43,2578.74 3799.21,2578.74 3900,2477.95 3900,1600 3900,-340 3840,-400
GND on Top Layer "Top-GND" (solid, remove dead copper, pour order 1): -35.43,-400 -35.43,2578.74 3799.21,2578.74 3900,2477.95 3900,1600 3900,-340 3840,-400

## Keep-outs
Top Layer:
  circle w1: c3800,100 r90
  circle w1: c2600,300 r90
  circle w1: c3550,2000 r90
  circle w1: c2600,1400 r90
  circle w1: c550,100 r90
Bottom Layer:
  circle w1: c3800,100 r90
  circle w1: c2600,300 r90
  circle w1: c3550,2000 r90
  circle w1: c2600,1400 r90
  circle w1: c550,100 r90
Keep-Out Layer:
  lines w2: 20,-400 3840,-400
  lines w5: 20,-400 -35.43,-344.57 -35.43,2464.57 78.74,2578.74 3799.21,2578.74 3900,2477.95 3900,1600 3900,50 ; 3840,-400 3900,-340 3900,50 ; 3900,50 3900,50

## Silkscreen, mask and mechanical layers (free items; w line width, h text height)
Top Overlay:
  lines w8: 84.8,643.78 -15,643.78 -15,1116.22 84.8,1116.22 ; 735.83,-282.2 735.83,-385 1208.27,-385 1208.27,-282.2 ; 3500,2175 3515,2175 3530,2190 3530,2310 3545,2325 3555,2325 ; 3600,2280 3555,2325 ; 3600,2370 3555,2325
  text "BOTTOM" at 1340,2560 h45 r270
  text "9v" at 1520,2515 h45
  text "9v" at 2020,2515 h45
  text "Sel" at 2490,2515 h45
  text "Sel" at 2990,2515 h45
  text "Sel" at 3660,2475 h45
  text "GND" at 3360,2450 h45
  text "TOP" at 760,2435 h45 r270
  text "9v" at 3790,2380 h45
  text "SDA" at 3360,2350 h45
  text "SCL" at 3360,2250 h45
  text "+LED PWR" at -10,2230 h45 r270
  text "5v" at 3790,2225 h45
  text "GROUND" at 430,2210 h60
  text "Vcc" at 3360,2150 h45
  text "AREF" at 910,2060 h25
  text "GND" at 1020,2060 h25
  text "D13" at 1110,2060 h25
  text "D12" at 1220,2060 h25
  text "D11" at 1320,2060 h25
  text "D10" at 1420,2060 h25
  text "D9" at 1530,2060 h25
  text "D6" at 1890,2060 h25
  text "D5" at 1970,2060 h25
  text "D4" at 2055,2060 h25
  text "D8" at 1620,1915 h25
  text "D7" at 1780,1915 h25
  text "D3" at 2180,1915 h25
  text "D2" at 2280,1915 h25
  text "TX0" at 2375,1915 h25
  text "RX0" at 2475,1915 h25
  text "TX3" at 2670,1915 h25
  text "RX3" at 2770,1915 h25
  text "TX2" at 2875,1915 h25
  text "RX2" at 2975,1915 h25
  text "TX1" at 3080,1915 h25
  text "RX1" at 3180,1915 h25
  text "SDA" at 3270,1915 h25
  text "SCL" at 3375,1915 h25
  text "-" at 2575,1565 h60 r270
  text "+" at 2720,1565 h60 r270
  text "GND" at 1355,1505 h45 r270
  text "STP" at 1555,1505 h45 r270
  text "DIR" at 1650,1505 h45 r270
  text "5v" at 1750,1490 h45 r270
  text "EN" at 1455,1485 h45 r270
  text "3V3" at 3540,1345 h25
  text "5V1" at 3825,1345 h25
  text "5V1" at 3825,1245 h25
  text "GND" at 3825,1150 h25
  text "Mot+" at 102.01,1094.37 h45 r270
  text "GND" at 16.01,1081.37 h45 r270
  text "TX" at 3825,1050 h25
  text "INT" at 3540,1045 h25
  text "RX" at 3825,950 h25
  text "EStop" at 102.01,874.37 h45 r270
  text "EStop" at 16.01,871.37 h45 r270
  text "TRIM" at 2275,485 h35
  text "RST" at 1260,160 h25
  text "3v3" at 1360,160 h25
  text "5v" at 1470,160 h25
  text "GND" at 1560,160 h25
  text "GND" at 1660,160 h25
  text "Vin" at 1770,160 h25
  text "AD0" at 1960,160 h25
  text "AD1" at 2060,160 h25
  text "AD2" at 2160,160 h25
  text "AD3" at 2260,160 h25
  text "AD4" at 2360,160 h25
  text "AD5" at 2460,160 h25
  text "AD6" at 2560,160 h25
  text "AD7" at 2660,160 h25
  text "PK0" at 2860,160 h25
  text "PK1" at 2970,160 h25
  text "PK2" at 3065,160 h25
  text "PK3" at 3165,160 h25
  text "PK4" at 3265,160 h25
  text "PK5" at 3365,160 h25
  text "PK6" at 3470,160 h25
  text "PK7" at 3570,160 h25
  text "Flow" at 1250,-85 h45
  text "Prs" at 2575,-90 h45
  text "Aux.Flow" at 3490,-100 h45
  text "RST" at 555,-135 h35
  text "9v" at 3490,-200 h45
  text "9v" at 1330.71,-202.76 h45
  text "5v" at 2585,-205 h45
  text "GND" at 555,-240 h35
  text "CHG+" at 774.37,-262.99 h45
  text "BAT+" at 1014.37,-262.99 h45
  text "GND" at 1285,-340 h45
  text "GND" at 3105,-340 h45
  text "GND" at 2195,-345 h45
  text "GND" at 794.37,-352.99 h45
  text "GND" at 1034.37,-352.99 h45
Mechanical 1:
  lines w8: 236.22,1259.84 393.7,1259.84 ; 393.7,1259.84 393.7,1732.28 -236.22,1732.28 -236.22,1259.84 393.7,1259.84 ; -78.74,157.48 -78.74,511.81 472.44,511.81 472.44,157.48 -78.74,157.48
